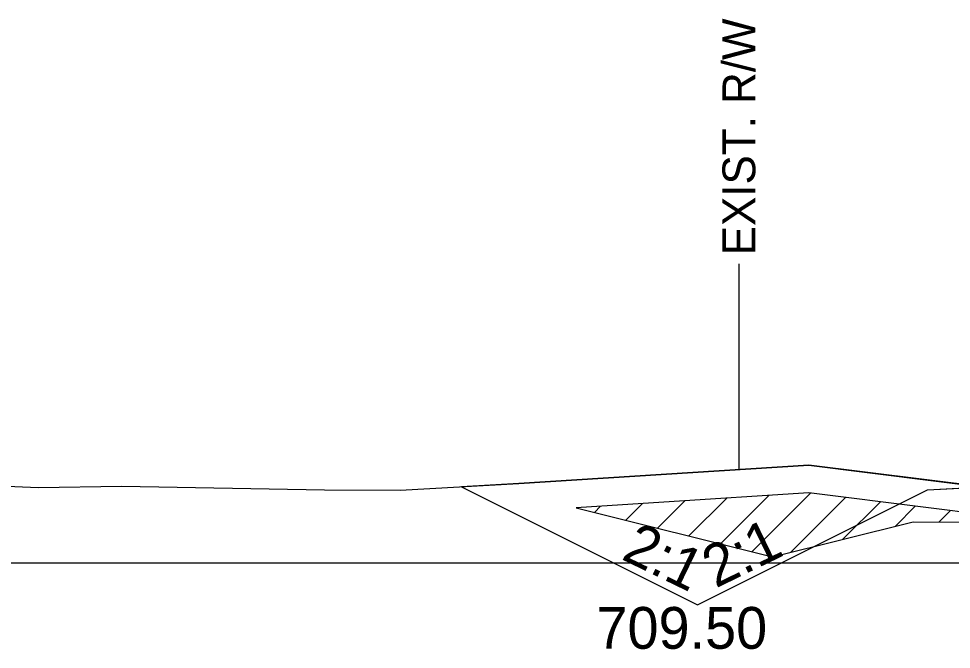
# Model space of a CAD drawing. Extents: x -26 to 4303, y -10 to 9577.
# Drawn here: x 1093.9 to 1127.42, y 6496.89 to 6519.57 of the extents above; entities that cross this region are included whole.
import ezdxf

# ---------------------------------------------------------------- set-up
doc = ezdxf.new("R2010")
doc.units = 0
for name, color, linetype in [('Old_Level_10', 7, 'Continuous'), ('Old_Level_2', 7, 'Continuous'), ('Pattern 1', 7, 'Continuous'), ('Prop CMT Concrete Wall', 7, 'Continuous'), ('Prop CMT Slope Grass', 7, 'Continuous'), ('Prop XS Ditch Standard Text', 7, 'Continuous'), ('Prop XS Earthwork Shape', 7, 'Continuous')]:
    doc.layers.add(name, color=color, linetype=linetype)

msp = doc.modelspace()

# ---------------------------------------------------------------- linework, layer by layer
at = {"layer": 'Old_Level_10'}
for p, q in [((1109.818, 6502.741), (1118.3, 6498.5)), ((1126.564, 6502.632), (1128.564, 6502.732)), ((1118.3, 6498.5), (1126.564, 6502.632))]:
    msp.add_line(p, q, dxfattribs=at)
at = {"layer": 'Old_Level_2'}
msp.add_line((1000, 6500), (1150, 6500), dxfattribs=at)
msp.add_line((1000, 6500), (1150, 6500), dxfattribs=at)
at = {"layer": 'Pattern 1'}
for p, q in [((1117.992, 6500.971), (1119.349, 6502.328)), ((1119.123, 6500.688), (1120.859, 6502.424)), ((1120.254, 6500.405), (1122.357, 6502.508)), ((1121.643, 6500.379), (1123.614, 6502.351)), ((1114.597, 6501.819), (1114.819, 6502.04)), ((1115.729, 6501.536), (1116.329, 6502.136)), ((1116.86, 6501.253), (1117.839, 6502.232)), ((1123.528, 6500.851), (1124.872, 6502.194)), ((1125.414, 6501.322), (1126.129, 6502.037)), ((1126.983, 6501.477), (1127.386, 6501.879))]:
    msp.add_line(p, q, dxfattribs=at)
msp.add_lwpolyline([(1121, 6500.218), (1126.057, 6501.483), (1130.367, 6501.455), (1128.597, 6501.728), (1126.512, 6501.989), (1122.297, 6502.516), (1117.089, 6502.185), (1113.937, 6501.984)], close=True, dxfattribs=at)
at = {"layer": 'Prop CMT Slope Grass'}
msp.add_lwpolyline([(1087.607, 6503.013), (1094.6, 6502.718), (1097.612, 6502.757), (1104.897, 6502.629), (1107.617, 6502.621), (1111.876, 6502.853), (1122.297, 6503.515), (1128.971, 6502.681)], dxfattribs=at)
at = {"layer": 'Prop XS Ditch Standard Text'}
msp.add_line((1119.787, 6510.757), (1119.787, 6503.356), dxfattribs=at)
at = {"layer": 'Prop XS Earthwork Shape'}
msp.add_lwpolyline([(1109.818, 6502.741), (1118.3, 6498.5), (1126.564, 6502.632), (1128.564, 6502.732), (1122.297, 6503.515), (1111.876, 6502.853)], close=True, dxfattribs=at)

# ---------------------------------------------------------------- texts
at = {"layer": 'Prop CMT Concrete Wall'}
for rotation, p in [(334.1383, (1115.522, 6500.157)), (25.8617, (1118.953, 6499.081))]:
    msp.add_text('2:1', height=1.5, rotation=rotation, dxfattribs=at).set_placement(p)
msp.add_text('709.50', height=1.5, dxfattribs=at).set_placement((1114.669, 6496.916))
at = {"layer": 'Prop XS Ditch Standard Text'}
msp.add_text('EXIST. R/W', height=1.1811, rotation=90, dxfattribs=at).set_placement((1120.378, 6511.059))

doc.saveas('drawing.dxf')
